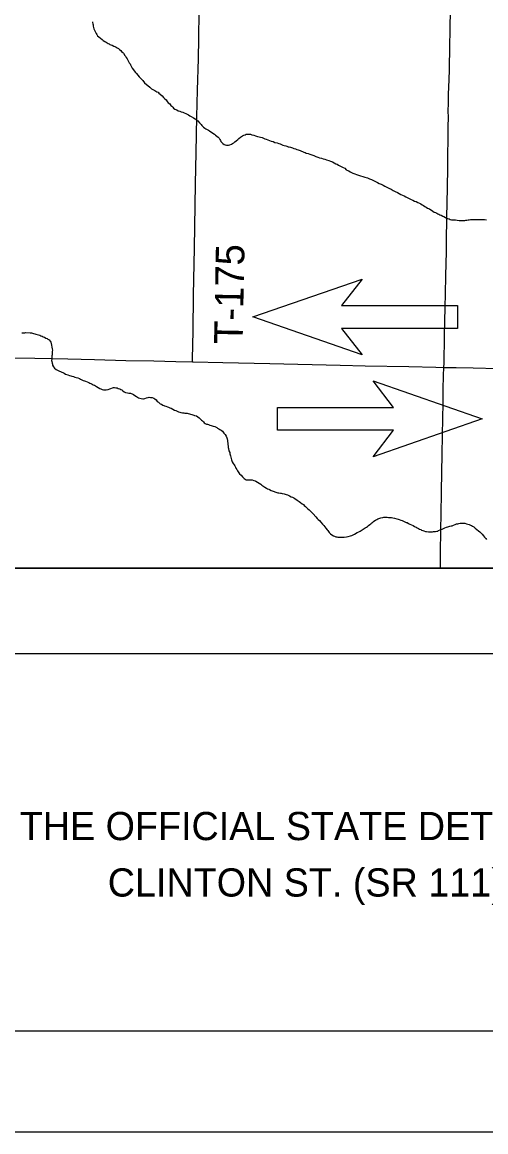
# Model space of a CAD drawing. Extents: x -483 to 680, y 0 to 440.
# Drawn here: x 131 to 177, y 0 to 110.1 of the extents above; entities that cross this region are included whole.
import ezdxf

# ---------------------------------------------------------------- set-up
doc = ezdxf.new("R2010")
doc.units = 0
for name, color, linetype in [('GM_X_Minor_River', 7, 'Continuous'), ('GM_X_State_Route', 7, 'Continuous'), ('GM_X_Township_Road', 7, 'Continuous'), ('GM_X_Township_Road_Text', 7, 'Continuous'), ('PM_P_Cells', 7, 'Continuous'), ('SH_Border', 7, 'Continuous'), ('SH_Cut_Line', 7, 'Continuous'), ('SH_Text', 7, 'Continuous')]:
    doc.layers.add(name, color=color, linetype=linetype)

msp = doc.modelspace()

# ---------------------------------------------------------------- linework, layer by layer
at = {"layer": 'GM_X_Minor_River'}
for points in [[(137.94, 110.19), (137.94, 110.1), (137.98, 109.98), (138, 109.89), (138.01, 109.76), (138.05, 109.62), (138.09, 109.49), (138.13, 109.36), (138.3, 109.03), (138.37, 108.92), (138.45, 108.8), (138.56, 108.67), (138.73, 108.54), (138.89, 108.42), (139.02, 108.31), (139.17, 108.21), (139.29, 108.14), (139.4, 108.08), (139.49, 108.02), (139.59, 107.98), (139.68, 107.93), (139.78, 107.89), (139.91, 107.85), (140.06, 107.77), (140.18, 107.74), (140.29, 107.66), (140.41, 107.6), (140.52, 107.53), (140.63, 107.43), (140.75, 107.33), (140.84, 107.24), (140.96, 107.14), (141.03, 107.05), (141.17, 106.84), (141.24, 106.74), (141.3, 106.65), (141.39, 106.5), (141.45, 106.38), (141.53, 106.25), (141.6, 106.12), (141.68, 106), (141.73, 105.91), (141.77, 105.79), (141.83, 105.7), (141.9, 105.58), (142.02, 105.41), (142.09, 105.32), (142.23, 105.14), (142.3, 105.03), (142.44, 104.88), (142.59, 104.72), (142.76, 104.55), (142.93, 104.34), (143.12, 104.13), (143.65, 103.7), (143.82, 103.54), (143.99, 103.43), (144.13, 103.35), (144.24, 103.29), (144.33, 103.24), (144.45, 103.18), (144.54, 103.1), (144.68, 103.01)], [(144.68, 103.01), (144.85, 102.84), (145, 102.68), (145.13, 102.53), (145.26, 102.42), (145.36, 102.28), (145.47, 102.15), (145.61, 102.02), (145.72, 101.88), (145.81, 101.79), (145.91, 101.71), (146, 101.62), (146.12, 101.52), (146.31, 101.43), (146.46, 101.35), (146.61, 101.31), (146.76, 101.25), (146.9, 101.2), (147.05, 101.14), (147.2, 101.08), (147.33, 101), (147.49, 100.93), (147.62, 100.85), (147.75, 100.77), (147.96, 100.64), (148.13, 100.53), (148.23, 100.47), (148.32, 100.41), (148.42, 100.34), (148.57, 100.16), (148.72, 99.99), (148.8, 99.9), (148.97, 99.71), (149.1, 99.63), (149.21, 99.55), (149.33, 99.48), (149.46, 99.42), (149.57, 99.34), (149.69, 99.27), (150.05, 99.02), (150.16, 98.92), (150.28, 98.83), (150.41, 98.71), (150.51, 98.62), (150.58, 98.5), (150.64, 98.41), (150.69, 98.31), (150.79, 98.2), (150.88, 98.09), (151.02, 97.99), (151.13, 97.95), (151.26, 97.93), (151.44, 97.93), (151.59, 97.97), (151.74, 98.04), (151.84, 98.1), (151.97, 98.18), (152.08, 98.25), (152.22, 98.37), (152.37, 98.5), (152.48, 98.59), (152.63, 98.73), (152.83, 98.86), (152.98, 98.93), (153.09, 98.97), (153.22, 99.01), (153.34, 99.03), (153.49, 99.03), (153.62, 99.01), (153.78, 98.97), (153.95, 98.93), (154.12, 98.87), (154.33, 98.8), (154.78, 98.68), (154.94, 98.62), (155.07, 98.57), (155.2, 98.53), (155.35, 98.47), (155.52, 98.39), (155.7, 98.34), (155.89, 98.28), (156.06, 98.2), (156.28, 98.15), (156.44, 98.09), (156.57, 98.05), (156.72, 97.99), (156.85, 97.93), (156.99, 97.9), (157.14, 97.86), (157.25, 97.82), (157.37, 97.78), (157.48, 97.76), (157.6, 97.72), (157.79, 97.67), (157.94, 97.61), (158.09, 97.57), (158.22, 97.51), (158.36, 97.47), (158.47, 97.44), (158.56, 97.4), (158.7, 97.34)], [(158.7, 97.34), (158.81, 97.3), (158.93, 97.24), (159.06, 97.21), (159.17, 97.15), (159.36, 97.09), (159.53, 97.03), (159.72, 96.96), (159.93, 96.9), (160.12, 96.82), (160.31, 96.75), (160.5, 96.69), (160.67, 96.63), (160.85, 96.57), (161, 96.53), (161.17, 96.48), (161.4, 96.42), (161.57, 96.34), (161.76, 96.27), (161.93, 96.19), (162.1, 96.09), (162.23, 96.04), (162.38, 95.96), (162.82, 95.73), (162.99, 95.64), (163.12, 95.5), (163.3, 95.43), (163.41, 95.37), (163.52, 95.29), (163.66, 95.23), (163.81, 95.16), (163.98, 95.1), (164.17, 95.02), (164.36, 94.97), (164.57, 94.89), (164.78, 94.83), (164.99, 94.77), (165.25, 94.68), (165.44, 94.6), (165.65, 94.51), (165.86, 94.41), (166.05, 94.33), (166.24, 94.24), (166.41, 94.14), (166.6, 94.05), (166.79, 93.97), (166.98, 93.87), (167.17, 93.78), (167.36, 93.65), (167.61, 93.55), (167.8, 93.44), (168.01, 93.32), (168.22, 93.23), (168.39, 93.15), (168.56, 93.05), (168.73, 92.98), (168.88, 92.9), (169.05, 92.8), (169.2, 92.73), (169.39, 92.63), (169.6, 92.54), (169.76, 92.46), (169.93, 92.38), (170.08, 92.33), (170.25, 92.25), (170.4, 92.17), (170.55, 92.1), (170.69, 92), (170.82, 91.93), (170.95, 91.85), (171.08, 91.77), (171.22, 91.68), (171.39, 91.6), (171.75, 91.37), (171.86, 91.29), (172, 91.24), (172.13, 91.18), (172.24, 91.12), (172.34, 91.08), (172.43, 91.03), (172.55, 90.97), (172.72, 90.89), (172.83, 90.84), (172.98, 90.76), (173.1, 90.7), (173.21, 90.66), (173.35, 90.61), (173.46, 90.57), (173.59, 90.53), (173.71, 90.51), (173.84, 90.51), (173.99, 90.51), (174.14, 90.49), (174.35, 90.47), (174.52, 90.47), (174.68, 90.47), (174.79, 90.47), (174.9, 90.47), (175, 90.49), (175.11, 90.49), (175.23, 90.51)], [(175.23, 90.51), (175.34, 90.52), (175.49, 90.54), (175.63, 90.54), (175.86, 90.56), (176.05, 90.56), (176.24, 90.56), (176.43, 90.54), (176.65, 90.54), (176.86, 90.54), (177.07, 90.52)], [(130.94, 79.29), (131.07, 79.29), (131.23, 79.31), (131.34, 79.33), (131.76, 79.31), (131.89, 79.29), (131.99, 79.27), (132.08, 79.25), (132.21, 79.21), (132.31, 79.17), (132.46, 79.13), (132.59, 79.1), (132.71, 79.06), (132.82, 79.02), (132.94, 78.98), (133.05, 78.9), (133.18, 78.87), (133.3, 78.79), (133.43, 78.73), (133.52, 78.69), (133.66, 78.6), (133.75, 78.48), (133.81, 78.37), (133.85, 78.24), (133.88, 78.08), (133.92, 77.89), (133.94, 77.72), (133.96, 77.57), (133.94, 77.46), (133.94, 77.31), (133.94, 77.13), (133.92, 77.02), (133.9, 76.93), (133.9, 76.74), (133.88, 76.56), (133.92, 76.45), (133.94, 76.3), (133.96, 76.18), (133.98, 76.09), (134.07, 75.92), (134.18, 75.8), (134.34, 75.67), (134.66, 75.5), (134.77, 75.46), (134.89, 75.4), (135, 75.36), (135.13, 75.31), (135.27, 75.19), (135.5, 75.13), (135.65, 75.08), (135.78, 75.04), (135.91, 75), (136.07, 74.96), (136.2, 74.92), (136.31, 74.88), (136.48, 74.83), (136.64, 74.77), (136.77, 74.71), (136.9, 74.65), (137.03, 74.58), (137.15, 74.54), (137.26, 74.5), (137.43, 74.43), (137.59, 74.37), (137.68, 74.31)], [(137.68, 74.31), (137.78, 74.27), (137.91, 74.21), (138, 74.14), (138.14, 74.1), (138.23, 74.04), (138.35, 73.97), (138.5, 73.87), (138.67, 73.78), (138.76, 73.74), (138.91, 73.68), (139.03, 73.66), (139.16, 73.64), (139.31, 73.64), (139.5, 73.68), (139.68, 73.75), (140.02, 73.89), (140.13, 73.88), (140.27, 73.85), (140.4, 73.83), (140.51, 73.79), (140.66, 73.73), (140.76, 73.69), (140.85, 73.65), (140.97, 73.56), (141.08, 73.46), (141.23, 73.39), (141.42, 73.35), (141.54, 73.33), (141.71, 73.31), (141.8, 73.29), (141.9, 73.25), (142.03, 73.18), (142.15, 73.1), (142.32, 72.97), (142.41, 72.91), (142.53, 72.85), (142.66, 72.81), (142.77, 72.79), (142.93, 72.77), (143.02, 72.77), (143.13, 72.79), (143.32, 72.85), (143.48, 72.89), (143.57, 72.91), (143.72, 72.9), (143.86, 72.87), (144.03, 72.81), (144.12, 72.75), (144.26, 72.64), (144.37, 72.5), (144.5, 72.41), (144.65, 72.27), (144.79, 72.22), (144.92, 72.12), (145.02, 72.08), (145.11, 72.05), (145.24, 72.01), (145.4, 71.97), (145.49, 71.93), (145.62, 71.87), (145.76, 71.82), (145.93, 71.74), (146.1, 71.64), (146.23, 71.59), (146.36, 71.53), (146.5, 71.47), (146.61, 71.43), (146.73, 71.39), (146.88, 71.37), (147.03, 71.36), (147.12, 71.34), (147.22, 71.34), (147.33, 71.32), (147.45, 71.3), (147.58, 71.26), (147.9, 71.16), (148, 71.14), (148.09, 71.11), (148.26, 71.05), (148.42, 70.97), (148.53, 70.86), (148.66, 70.72), (148.78, 70.65), (148.87, 70.57), (148.97, 70.48), (149.04, 70.38), (149.14, 70.3), (149.27, 70.25), (149.37, 70.23), (149.48, 70.19), (149.59, 70.15), (149.73, 70.11), (149.84, 70.07), (149.94, 70.05), (150.09, 70), (150.28, 69.9), (150.37, 69.84), (150.49, 69.79), (150.6, 69.71), (150.71, 69.65)], [(150.71, 69.65), (150.85, 69.54), (150.92, 69.44), (151, 69.35), (151.11, 69.2), (151.23, 69.04), (151.3, 68.89), (151.32, 68.8), (151.34, 68.62), (151.36, 68.51), (151.38, 68.34), (151.43, 67.92), (151.45, 67.81), (151.49, 67.6), (151.57, 67.43), (151.58, 67.29), (151.62, 67.2), (151.66, 67.08), (151.68, 66.97), (151.74, 66.7), (151.83, 66.51), (151.92, 66.34), (152, 66.19), (152.08, 66.09), (152.15, 65.96), (152.19, 65.87), (152.27, 65.73), (152.34, 65.6), (152.42, 65.5), (152.55, 65.31), (152.7, 65.18), (152.85, 65.01), (152.99, 64.86), (153.1, 64.78), (153.21, 64.72), (153.31, 64.7), (153.44, 64.7), (153.58, 64.72), (153.69, 64.72), (153.8, 64.7), (153.96, 64.66), (154.09, 64.63), (154.18, 64.57), (154.34, 64.47), (154.51, 64.38), (154.66, 64.28), (154.77, 64.19), (155.06, 63.98), (155.23, 63.88), (155.32, 63.82), (155.44, 63.79), (155.53, 63.75), (155.68, 63.65), (155.78, 63.63), (155.97, 63.56), (156.06, 63.52), (156.16, 63.5), (156.25, 63.46), (156.35, 63.44), (156.44, 63.42), (156.6, 63.38), (156.69, 63.38), (156.79, 63.36), (156.98, 63.32), (157.07, 63.29), (157.19, 63.25), (157.3, 63.23), (157.51, 63.11), (157.68, 63.04), (157.81, 62.98), (157.95, 62.92), (158.04, 62.87), (158.27, 62.71), (158.36, 62.64), (158.48, 62.56), (158.59, 62.48), (158.78, 62.33), (158.88, 62.25), (158.97, 62.16), (159.08, 62.06), (159.2, 61.97), (159.29, 61.87), (159.46, 61.72), (159.56, 61.63), (159.65, 61.53), (159.75, 61.43), (159.84, 61.34), (160.11, 61.05), (160.24, 60.88), (160.36, 60.77), (160.47, 60.67), (160.62, 60.5), (160.79, 60.31), (160.91, 60.18), (161, 60.06), (161.11, 59.93), (161.23, 59.76), (161.32, 59.68), (161.38, 59.59), (161.46, 59.49), (161.59, 59.34)], [(161.59, 59.34), (161.7, 59.24), (161.87, 59.15), (161.99, 59.11), (162.1, 59.07), (162.2, 59.05), (162.31, 59.03), (162.48, 59.01), (162.58, 59.01), (162.67, 59.01), (162.79, 59.01), (162.94, 59.01), (163.15, 59.07), (163.34, 59.09), (163.55, 59.14), (163.68, 59.2), (163.97, 59.33), (164.23, 59.48), (164.38, 59.56), (164.52, 59.63), (164.63, 59.69), (165.03, 59.94), (165.16, 60.01), (165.26, 60.09), (165.36, 60.18), (165.47, 60.28), (165.58, 60.35), (165.68, 60.43), (165.79, 60.52), (165.89, 60.6), (166.04, 60.71), (166.17, 60.79), (166.27, 60.83), (166.36, 60.86), (166.48, 60.9), (166.59, 60.94), (166.76, 60.98), (166.86, 61), (166.97, 61), (167.07, 61.01), (167.2, 61.01), (167.35, 60.98), (167.47, 60.97), (167.62, 60.96), (167.75, 60.94), (167.92, 60.92), (168.17, 60.84), (168.3, 60.82), (168.4, 60.78), (168.55, 60.72), (168.68, 60.67), (168.97, 60.55), (169.1, 60.49), (169.2, 60.48), (169.31, 60.38), (169.44, 60.32), (169.8, 60.17), (169.92, 60.09), (170.07, 60.02), (170.18, 59.94), (170.3, 59.88), (170.41, 59.83), (170.53, 59.77), (170.62, 59.73), (170.74, 59.69), (170.83, 59.65), (171, 59.6), (171.12, 59.58), (171.31, 59.56), (171.4, 59.56), (171.55, 59.56), (171.71, 59.56), (171.8, 59.57), (171.99, 59.59), (172.12, 59.61), (172.22, 59.63), (172.31, 59.67), (172.48, 59.74), (172.58, 59.78), (172.68, 59.82), (172.85, 59.91), (172.94, 59.95), (173.09, 60.03), (173.23, 60.06), (173.44, 60.12), (173.57, 60.14), (173.66, 60.16), (173.8, 60.23), (173.95, 60.29), (174.1, 60.33), (174.22, 60.35), (174.33, 60.38), (174.46, 60.4), (174.79, 60.42), (174.9, 60.4), (175.09, 60.36), (175.22, 60.32), (175.36, 60.27), (175.49, 60.23), (175.59, 60.19), (175.68, 60.11)], [(175.68, 60.11), (175.81, 60.04), (175.93, 59.92), (176.1, 59.79), (176.27, 59.66), (176.4, 59.56), (176.53, 59.41), (176.63, 59.31), (176.78, 59.14), (176.86, 59.01), (176.99, 58.88), (177.08, 58.8)]]:
    msp.add_lwpolyline(points, dxfattribs=at)
at = {"layer": 'GM_X_State_Route'}
msp.add_lwpolyline([(127.57, 76.84), (132.23, 76.79), (135.5, 76.72), (138.14, 76.65), (141.25, 76.57), (144.04, 76.51), (146.22, 76.46), (147.89, 76.41), (147.93, 76.41), (150.88, 76.36), (155.54, 76.26), (162.54, 76.1), (165.02, 76.04), (169.37, 75.95), (172.02, 75.9), (172.84, 75.88), (174.04, 75.85), (175.75, 75.83), (178.23, 75.78)], dxfattribs=at)
at = {"layer": 'GM_X_Township_Road'}
for points in [[(172.84, 75.88), (172.86, 76.31), (172.89, 78.95), (172.96, 81.9), (172.98, 83.14), (173.03, 85), (173.08, 87.33), (173.09, 88.42), (173.13, 90.75), (173.18, 93.7), (173.22, 95.72), (173.24, 97.12), (173.26, 98.37), (173.27, 99.76), (173.28, 100.7), (173.27, 101.32), (173.28, 102.1), (173.29, 102.72), (173.3, 103.03), (173.31, 103.65), (173.38, 105.36), (173.39, 105.83), (173.42, 107.38), (173.47, 109.71), (173.56, 114.06)], [(147.89, 76.41), (147.89, 76.7), (147.93, 79.49), (147.99, 83.06), (148.07, 87.72), (148.18, 94.09), (148.24, 97.19), (148.32, 100.76), (148.38, 103.4), (148.46, 106.5), (148.49, 108.52), (148.54, 111.16), (148.55, 111.82)], [(172.49, 55.95), (172.51, 57.35), (172.54, 59.84), (172.56, 61.24), (172.6, 63.57), (172.67, 67.3), (172.74, 70.87), (172.76, 72.27), (172.78, 73.67), (172.81, 75.06), (172.84, 75.88)]]:
    msp.add_lwpolyline(points, dxfattribs=at)
at = {"layer": 'PM_P_Cells'}
for p, q in [((153.88, 80.88), (164.72, 84.64)), ((164.72, 84.64), (162.68, 82.01)), ((162.68, 82.01), (174.2, 82.01)), ((174.2, 82.01), (174.2, 79.75)), ((164.72, 77.12), (153.88, 80.88)), ((174.2, 79.75), (162.68, 79.75)), ((162.68, 79.75), (164.72, 77.12)), ((165.8, 74.53), (176.64, 70.77)), ((167.83, 71.9), (165.8, 74.53)), ((156.32, 69.64), (156.32, 71.9)), ((156.32, 71.9), (167.83, 71.9)), ((176.64, 70.77), (165.8, 67)), ((167.83, 69.64), (156.32, 69.64)), ((165.8, 67), (167.83, 69.64))]:
    msp.add_line(p, q, dxfattribs=at)
at = {"layer": 'SH_Border'}
msp.add_lwpolyline([(30, 430), (670, 430), (670, 10), (30, 10)], close=True, dxfattribs=at)
at = {"layer": 'SH_Cut_Line'}
msp.add_lwpolyline([(0, 0), (680, 0), (680, 440), (0, 440)], close=True, dxfattribs=at)
msp.add_lwpolyline([(45.61, 281.49), (45.61, 55.95), (373.8, 55.95)], dxfattribs=at)
at = {"layer": 'SH_Text'}
for points in [[(37.11, 404.45), (394.11, 404.45), (394.11, 47.45), (37.11, 47.45)], [(45.61, 395.95), (385.61, 395.95), (385.61, 55.95), (45.61, 55.95)]]:
    msp.add_lwpolyline(points, close=True, dxfattribs=at)

# ---------------------------------------------------------------- texts
at = {"layer": 'GM_X_Township_Road_Text'}
msp.add_text('T-175', height=2.841, rotation=88.877, dxfattribs=at).set_placement((152.85, 78.16))
at = {"layer": 'SH_Text'}
for s, p in [('NOTE: THE OFFICIAL STATE DETOUR IS TO FOLLOW THE SR 111 TRUCK ROUTE WITHIN THE CITY OF DEFIANCE.', (118.24, 28.95)), ('CLINTON ST. (SR 111) - DEATRICK ST. - HOLGATE AVE. - 3RD ST. - CLINTON ST. (SR 111)', (139.46, 23.35))]:
    msp.add_text(s, height=2.8, dxfattribs=at).set_placement(p)

doc.saveas('drawing.dxf')
